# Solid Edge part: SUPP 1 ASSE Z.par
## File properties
Subject: SUPP 1 ASSE Z
Author: f_grande
Template: Normal.par
Last saved by: f_grande
Revision: 4
Application: Solid Edge
Material: MDF
Stile della faccia: Marroncino
Coef. of Thermal Exp: 0.0
Thermal Conductivity: 0.0
Specific Heat: 0.0
Modulus of Elasticity: 0.0
Poisson's Ratio: 0.0
Yield Stress: 0.0
Ultimate Stress: 0.0
Elongation: 0.0
Tipo di contenuto documento: 0
Densità: 750,000 kg/m^3
Precisione: 0,99
Document Number: KR0129
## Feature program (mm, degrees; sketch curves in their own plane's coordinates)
sketch for "unnamed Protrusion 1" plane through (0, 0, 0) normal (0, -1, 0) x-axis (1, 0, 0)
  line (-109.4019, 165.2947) -> (19.5981, 165.2947)
  line (19.5981, 165.2947) -> (19.5981, -37.7053)
  line (19.5981, -37.7053) -> (-109.4019, -37.7053)
  line (-109.4019, -37.7053) -> (-109.4019, 165.2947)
  dimension (linear) = 19.5981
  dimension (linear) = 19.5981
extrude "unnamed Protrusion 1" add finite 19 along +normal
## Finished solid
Body 1: solid body, 6 faces, 12 edges, 8 vertices.
  Faces by surface: plane 6
  Edges by curve: line 12
Bounding box of the edges (mm): 129.000 x 19.000 x 203.000, from (-109.4019, -19, -37.7053) to (19.5981, 0, 165.2947).
Planar faces by outward normal: +x 1, +y 1, +z 1, -x 1, -y 1, -z 1
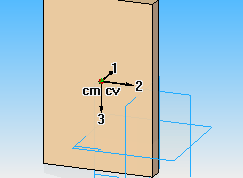
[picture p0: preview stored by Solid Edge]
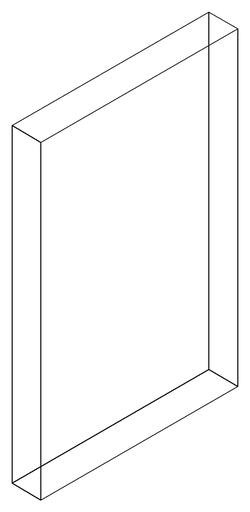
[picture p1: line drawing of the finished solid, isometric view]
